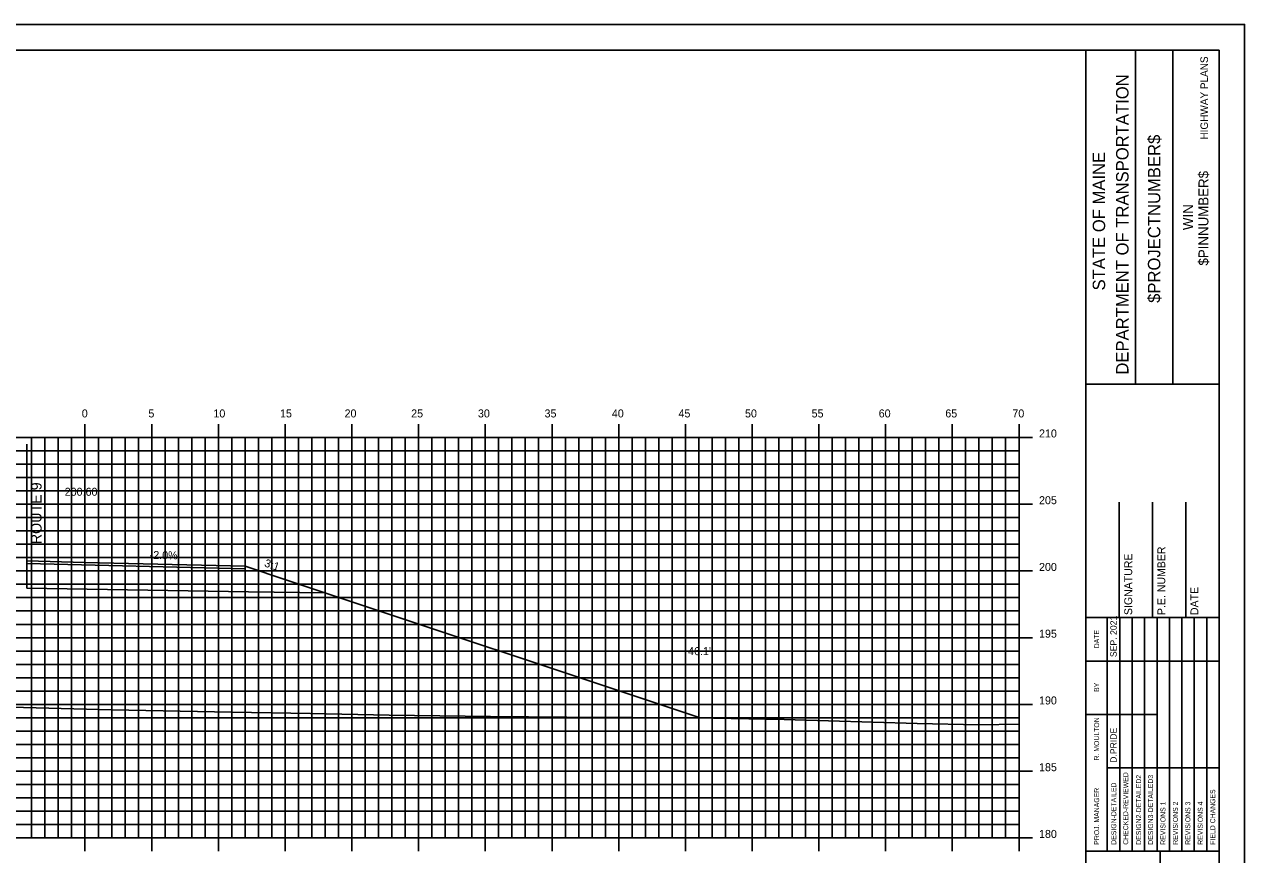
# Model space of a CAD drawing. Extents: x 1723074 to 1723246, y 459560 to 459670.
# Drawn here: x 1723152.9 to 1723244.4, y 459607.4 to 459669.6 of the extents above; entities that cross this region are included whole.
import ezdxf

# ---------------------------------------------------------------- set-up
doc = ezdxf.new("R2010")
doc.units = 0
for name, color, linetype in [('ANNOTATION', 7, 'Continuous'), ('BORDER', 7, 'Continuous'), ('D_Roadway_Centerline_Text', 7, 'Continuous'), ('D_Roadway_Drive_Gravel', 7, 'Continuous'), ('D_Roadway_Edge_Shoulder', 7, 'Continuous'), ('D_Roadway_Edge_TW', 7, 'Continuous'), ('D_Roadway_Pavement', 7, 'Continuous'), ('D_Roadway_SlopeLines', 7, 'Continuous'), ('D_Roadway_SubGrade', 7, 'Continuous'), ('D_Text_Standard', 7, 'Continuous'), ('H_V ANNOTATION', 7, 'Continuous'), ('HIGHWAY_TITLE', 7, 'Continuous'), ('MAJOR', 7, 'Continuous'), ('MINOR', 7, 'Continuous'), ('PLOT BOUNDARY', 7, 'Continuous'), ('S_Roadway_Centerline', 7, 'Continuous')]:
    doc.layers.add(name, color=color, linetype=linetype)

msp = doc.modelspace()

# ---------------------------------------------------------------- linework, layer by layer
at = {"layer": 'BORDER'}
for p, q in [((1723232.447, 459562.613), (1723232.447, 459667.613)), ((1723236.176, 459642.61), (1723236.176, 459667.61)), ((1723238.971, 459642.61), (1723238.971, 459667.61)), ((1723232.448, 459642.607), (1723242.447, 459642.607)), ((1723234.947, 459625.116), (1723234.947, 459633.763)), ((1723237.447, 459625.116), (1723237.447, 459633.763)), ((1723239.947, 459625.116), (1723239.947, 459633.763)), ((1723232.447, 459625.116), (1723242.447, 459625.116)), ((1723232.447, 459607.616), (1723242.447, 459607.616)), ((1723238.038, 459572.616), (1723238.038, 459607.616))]:
    msp.add_line(p, q, dxfattribs=at)
msp.add_lwpolyline([(1723082.447, 459562.613), (1723242.447, 459562.613), (1723242.447, 459667.613), (1723082.447, 459667.613)], close=True, dxfattribs=at)
for points in [[(1723234.062, 459621.866), (1723234.062, 459625.116)], [(1723234.995, 459607.619), (1723234.995, 459625.116)], [(1723235.926, 459625.116), (1723235.926, 459607.619)], [(1723236.858, 459607.619), (1723236.858, 459625.116)], [(1723237.79, 459607.619), (1723237.79, 459625.116)], [(1723238.721, 459607.619), (1723238.721, 459625.116)], [(1723239.653, 459607.619), (1723239.653, 459625.116)], [(1723240.585, 459607.619), (1723240.585, 459625.116)], [(1723241.516, 459607.619), (1723241.516, 459625.116)], [(1723234.063, 459607.619), (1723234.063, 459624.41)], [(1723232.447, 459621.866), (1723242.447, 459621.866)], [(1723232.447, 459617.866), (1723234.063, 459617.866)], [(1723234.062, 459617.866), (1723237.789, 459617.866)], [(1723234.062, 459613.866), (1723242.447, 459613.866)]]:
    msp.add_lwpolyline(points, dxfattribs=at)
at = {"layer": 'D_Roadway_Drive_Gravel'}
msp.add_line((1723169.447, 459628.973), (1723172.638, 459627.909), dxfattribs=at)
at = {"layer": 'D_Roadway_Edge_Shoulder'}
msp.add_line((1723157.447, 459629.258), (1723153.095, 459629.361), dxfattribs=at)
msp.add_lwpolyline([(1723153.095, 459629.165), (1723169.447, 459628.777), (1723169.447, 459628.973)], dxfattribs=at)
at = {"layer": 'D_Roadway_Edge_TW'}
msp.add_line((1723153.095, 459629.415), (1723153.095, 459629.165), dxfattribs=at)
msp.add_line((1723153.095, 459629.415), (1723153.095, 459629.165), dxfattribs=at)
msp.add_line((1723153.095, 459629.415), (1723153.095, 459629.165), dxfattribs=at)
at = {"layer": 'D_Roadway_Pavement'}
msp.add_line((1723153.095, 459629.165), (1723153.095, 459628.748), dxfattribs=at)
msp.add_line((1723153.095, 459629.165), (1723153.095, 459628.748), dxfattribs=at)
msp.add_lwpolyline([(1723153.095, 459629.165), (1723153.095, 459628.748)], dxfattribs=at)
at = {"layer": 'D_Roadway_SlopeLines'}
msp.add_lwpolyline([(1723169.447, 459628.973), (1723172.638, 459627.909), (1723203.544, 459617.607)], dxfattribs=at)
at = {"layer": 'D_Roadway_SubGrade'}
for p, q in [((1723153.095, 459638.114), (1723153.095, 459627.332)), ((1723153.095, 459629.165), (1723153.095, 459627.332)), ((1723157.447, 459629.258), (1723169.447, 459628.973)), ((1723153.095, 459627.332), (1723169.703, 459627.059)), ((1723169.703, 459627.059), (1723175.474, 459626.964))]:
    msp.add_line(p, q, dxfattribs=at)
msp.add_lwpolyline([(1723153.095, 459628.748), (1723153.095, 459629.165), (1723153.095, 459627.332)], dxfattribs=at)
at = {"layer": 'MAJOR'}
for p, q in [((1723157.447, 459639.615), (1723157.447, 459638.613)), ((1723162.447, 459639.615), (1723162.447, 459638.613)), ((1723167.447, 459639.615), (1723167.447, 459638.613)), ((1723172.447, 459639.615), (1723172.447, 459638.613)), ((1723177.447, 459639.615), (1723177.447, 459638.613)), ((1723182.447, 459639.615), (1723182.447, 459638.613)), ((1723187.447, 459639.615), (1723187.447, 459638.613)), ((1723192.447, 459639.615), (1723192.447, 459638.613)), ((1723197.447, 459639.615), (1723197.447, 459638.613)), ((1723202.447, 459639.615), (1723202.447, 459638.613)), ((1723207.447, 459639.615), (1723207.447, 459638.613)), ((1723212.447, 459639.615), (1723212.447, 459638.613)), ((1723217.447, 459639.615), (1723217.447, 459638.613)), ((1723222.447, 459639.615), (1723222.447, 459638.613)), ((1723227.447, 459639.615), (1723227.447, 459638.613)), ((1723087.447, 459638.613), (1723227.447, 459638.613)), ((1723087.447, 459638.613), (1723227.447, 459638.613)), ((1723157.447, 459608.613), (1723157.447, 459638.613)), ((1723162.447, 459608.613), (1723162.447, 459638.613)), ((1723167.447, 459608.613), (1723167.447, 459638.613)), ((1723172.447, 459608.613), (1723172.447, 459638.613)), ((1723177.447, 459608.613), (1723177.447, 459638.613)), ((1723182.447, 459608.613), (1723182.447, 459638.613)), ((1723187.447, 459608.613), (1723187.447, 459638.613)), ((1723192.447, 459608.613), (1723192.447, 459638.613)), ((1723197.447, 459608.613), (1723197.447, 459638.613)), ((1723202.447, 459608.613), (1723202.447, 459638.613)), ((1723207.447, 459608.613), (1723207.447, 459638.613)), ((1723212.447, 459608.613), (1723212.447, 459638.613)), ((1723217.447, 459608.613), (1723217.447, 459638.613)), ((1723222.447, 459608.613), (1723222.447, 459638.613)), ((1723228.449, 459638.613), (1723226.445, 459638.613)), ((1723227.447, 459608.613), (1723227.447, 459638.613)), ((1723227.447, 459608.613), (1723227.447, 459638.613)), ((1723087.447, 459633.613), (1723227.447, 459633.613)), ((1723228.449, 459633.613), (1723226.445, 459633.613)), ((1723087.447, 459628.613), (1723227.447, 459628.613)), ((1723228.449, 459628.613), (1723226.445, 459628.613)), ((1723087.447, 459623.613), (1723227.447, 459623.613)), ((1723228.449, 459623.613), (1723226.445, 459623.613)), ((1723087.447, 459618.613), (1723227.447, 459618.613)), ((1723228.449, 459618.613), (1723226.445, 459618.613)), ((1723087.447, 459613.613), (1723227.447, 459613.613)), ((1723228.449, 459613.613), (1723226.445, 459613.613)), ((1723087.447, 459608.613), (1723227.447, 459608.613)), ((1723087.447, 459608.613), (1723227.447, 459608.613)), ((1723157.447, 459607.611), (1723157.447, 459608.613)), ((1723162.447, 459607.611), (1723162.447, 459608.613)), ((1723167.447, 459607.611), (1723167.447, 459608.613)), ((1723172.447, 459607.611), (1723172.447, 459608.613)), ((1723177.447, 459607.611), (1723177.447, 459608.613)), ((1723182.447, 459607.611), (1723182.447, 459608.613)), ((1723187.447, 459607.611), (1723187.447, 459608.613)), ((1723192.447, 459607.611), (1723192.447, 459608.613)), ((1723197.447, 459607.611), (1723197.447, 459608.613)), ((1723202.447, 459607.611), (1723202.447, 459608.613)), ((1723207.447, 459607.611), (1723207.447, 459608.613)), ((1723212.447, 459607.611), (1723212.447, 459608.613)), ((1723217.447, 459607.611), (1723217.447, 459608.613)), ((1723222.447, 459607.611), (1723222.447, 459608.613)), ((1723228.449, 459608.613), (1723226.445, 459608.613)), ((1723227.447, 459607.611), (1723227.447, 459608.613))]:
    msp.add_line(p, q, dxfattribs=at)
at = {"layer": 'MINOR'}
for p, q in [((1723153.447, 459608.613), (1723153.447, 459638.613)), ((1723154.447, 459608.613), (1723154.447, 459638.613)), ((1723155.447, 459608.613), (1723155.447, 459638.613)), ((1723156.447, 459608.613), (1723156.447, 459638.613)), ((1723158.447, 459608.613), (1723158.447, 459638.613)), ((1723159.447, 459608.613), (1723159.447, 459638.613)), ((1723160.447, 459608.613), (1723160.447, 459638.613)), ((1723161.447, 459608.613), (1723161.447, 459638.613)), ((1723163.447, 459608.613), (1723163.447, 459638.613)), ((1723164.447, 459608.613), (1723164.447, 459638.613)), ((1723165.447, 459608.613), (1723165.447, 459638.613)), ((1723166.447, 459608.613), (1723166.447, 459638.613)), ((1723168.447, 459608.613), (1723168.447, 459638.613)), ((1723169.447, 459608.613), (1723169.447, 459638.613)), ((1723170.447, 459608.613), (1723170.447, 459638.613)), ((1723171.447, 459608.613), (1723171.447, 459638.613)), ((1723173.447, 459608.613), (1723173.447, 459638.613)), ((1723174.447, 459608.613), (1723174.447, 459638.613)), ((1723175.447, 459608.613), (1723175.447, 459638.613)), ((1723176.447, 459608.613), (1723176.447, 459638.613)), ((1723178.447, 459608.613), (1723178.447, 459638.613)), ((1723179.447, 459608.613), (1723179.447, 459638.613)), ((1723180.447, 459608.613), (1723180.447, 459638.613)), ((1723181.447, 459608.613), (1723181.447, 459638.613)), ((1723183.447, 459608.613), (1723183.447, 459638.613)), ((1723184.447, 459608.613), (1723184.447, 459638.613)), ((1723185.447, 459608.613), (1723185.447, 459638.613)), ((1723186.447, 459608.613), (1723186.447, 459638.613)), ((1723188.447, 459608.613), (1723188.447, 459638.613)), ((1723189.447, 459608.613), (1723189.447, 459638.613)), ((1723190.447, 459608.613), (1723190.447, 459638.613)), ((1723191.447, 459608.613), (1723191.447, 459638.613)), ((1723193.447, 459608.613), (1723193.447, 459638.613)), ((1723194.447, 459608.613), (1723194.447, 459638.613)), ((1723195.447, 459608.613), (1723195.447, 459638.613)), ((1723196.447, 459608.613), (1723196.447, 459638.613)), ((1723198.447, 459608.613), (1723198.447, 459638.613)), ((1723199.447, 459608.613), (1723199.447, 459638.613)), ((1723200.447, 459608.613), (1723200.447, 459638.613)), ((1723201.447, 459608.613), (1723201.447, 459638.613)), ((1723203.447, 459608.613), (1723203.447, 459638.613)), ((1723204.447, 459608.613), (1723204.447, 459638.613)), ((1723205.447, 459608.613), (1723205.447, 459638.613)), ((1723206.447, 459608.613), (1723206.447, 459638.613)), ((1723208.447, 459608.613), (1723208.447, 459638.613)), ((1723209.447, 459608.613), (1723209.447, 459638.613)), ((1723210.447, 459608.613), (1723210.447, 459638.613)), ((1723211.447, 459608.613), (1723211.447, 459638.613)), ((1723213.447, 459608.613), (1723213.447, 459638.613)), ((1723214.447, 459608.613), (1723214.447, 459638.613)), ((1723215.447, 459608.613), (1723215.447, 459638.613)), ((1723216.447, 459608.613), (1723216.447, 459638.613)), ((1723218.447, 459608.613), (1723218.447, 459638.613)), ((1723219.447, 459608.613), (1723219.447, 459638.613)), ((1723220.447, 459608.613), (1723220.447, 459638.613)), ((1723221.447, 459608.613), (1723221.447, 459638.613)), ((1723223.447, 459608.613), (1723223.447, 459638.613)), ((1723224.447, 459608.613), (1723224.447, 459638.613)), ((1723225.447, 459608.613), (1723225.447, 459638.613)), ((1723226.447, 459608.613), (1723226.447, 459638.613)), ((1723087.447, 459637.613), (1723227.447, 459637.613)), ((1723227.447, 459637.613), (1723226.445, 459637.613)), ((1723087.447, 459636.613), (1723227.447, 459636.613)), ((1723227.447, 459636.613), (1723226.445, 459636.613)), ((1723087.447, 459635.613), (1723227.447, 459635.613)), ((1723227.447, 459635.613), (1723226.445, 459635.613)), ((1723087.447, 459634.613), (1723227.447, 459634.613)), ((1723227.447, 459634.613), (1723226.445, 459634.613)), ((1723087.447, 459632.613), (1723227.447, 459632.613)), ((1723227.447, 459632.613), (1723226.445, 459632.613)), ((1723087.447, 459631.613), (1723227.447, 459631.613)), ((1723227.447, 459631.613), (1723226.445, 459631.613)), ((1723087.447, 459630.613), (1723227.447, 459630.613)), ((1723227.447, 459630.613), (1723226.445, 459630.613)), ((1723087.447, 459629.613), (1723227.447, 459629.613)), ((1723227.447, 459629.613), (1723226.445, 459629.613)), ((1723087.447, 459627.613), (1723227.447, 459627.613)), ((1723227.447, 459627.613), (1723226.445, 459627.613)), ((1723087.447, 459626.613), (1723227.447, 459626.613)), ((1723227.447, 459626.613), (1723226.445, 459626.613)), ((1723087.447, 459625.613), (1723227.447, 459625.613)), ((1723227.447, 459625.613), (1723226.445, 459625.613)), ((1723087.447, 459624.613), (1723227.447, 459624.613)), ((1723227.447, 459624.613), (1723226.445, 459624.613)), ((1723087.447, 459622.613), (1723227.447, 459622.613)), ((1723227.447, 459622.613), (1723226.445, 459622.613)), ((1723087.447, 459621.613), (1723227.447, 459621.613)), ((1723227.447, 459621.613), (1723226.445, 459621.613)), ((1723087.447, 459620.613), (1723227.447, 459620.613)), ((1723227.447, 459620.613), (1723226.445, 459620.613)), ((1723087.447, 459619.613), (1723227.447, 459619.613)), ((1723227.447, 459619.613), (1723226.445, 459619.613)), ((1723087.447, 459617.613), (1723227.447, 459617.613)), ((1723227.447, 459617.613), (1723226.445, 459617.613)), ((1723087.447, 459616.613), (1723227.447, 459616.613)), ((1723227.447, 459616.613), (1723226.445, 459616.613)), ((1723087.447, 459615.613), (1723227.447, 459615.613)), ((1723227.447, 459615.613), (1723226.445, 459615.613)), ((1723087.447, 459614.613), (1723227.447, 459614.613)), ((1723227.447, 459614.613), (1723226.445, 459614.613)), ((1723087.447, 459612.613), (1723227.447, 459612.613)), ((1723227.447, 459612.613), (1723226.445, 459612.613)), ((1723087.447, 459611.613), (1723227.447, 459611.613)), ((1723227.447, 459611.613), (1723226.445, 459611.613)), ((1723087.447, 459610.613), (1723227.447, 459610.613)), ((1723227.447, 459610.613), (1723226.445, 459610.613)), ((1723087.447, 459609.613), (1723227.447, 459609.613)), ((1723227.447, 459609.613), (1723226.445, 459609.613))]:
    msp.add_line(p, q, dxfattribs=at)
at = {"layer": 'PLOT BOUNDARY'}
msp.add_lwpolyline([(1723074.354, 459559.554), (1723244.354, 459559.554), (1723244.354, 459669.554), (1723074.354, 459669.554)], close=True, dxfattribs=at)
at = {"layer": 'S_Roadway_Centerline'}
msp.add_lwpolyline([(1723087.447, 459619.698), (1723092.56, 459619.553), (1723093.807, 459619.518), (1723094.981, 459619.479), (1723105.508, 459619.487), (1723116.371, 459619.255), (1723116.981, 459619.238), (1723117.588, 459619.206), (1723137.522, 459618.752), (1723140.372, 459618.688), (1723143.416, 459618.636), (1723159.426, 459618.214), (1723168.45, 459618.026), (1723174.35, 459617.946), (1723180.246, 459617.813), (1723187.846, 459617.713), (1723193.553, 459617.67), (1723203.226, 459617.613), (1723209.857, 459617.477), (1723219.824, 459617.188), (1723224.448, 459617.09), (1723227.447, 459617.142)], dxfattribs=at)

# ---------------------------------------------------------------- texts
at = {"layer": 'ANNOTATION'}
for s, height, rotation, p in [('ROUTE 9', 0.8, 90, (1723154.193, 459630.613)), ('-2.0%', 0.6, 358.85424, (1723162.29, 459629.516)), ('3:1', 0.6, 341.56505, (1723170.845, 459628.961))]:
    msp.add_text(s, height=height, rotation=rotation, dxfattribs=at).set_placement(p)
at = {"layer": 'BORDER'}
for s, height, p in [('DEPARTMENT OF TRANSPORTATION', 0.93176, (1723235.654, 459643.319)), ('$PROJECTNUMBER$', 0.93176, (1723238.039, 459648.692)), ('STATE OF MAINE', 0.93176, (1723233.902, 459649.625)), ('$PINNUMBER$', 0.74527, (1723241.643, 459651.488)), ('WIN', 0.7453, (1723240.484, 459654.143)), ('SIGNATURE', 0.5906, (1723235.928, 459625.308)), ('P.E. NUMBER', 0.59055, (1723238.408, 459625.308)), ('DATE', 0.5906, (1723240.888, 459625.308)), ('SEP. 2021', 0.4845, (1723234.77, 459622.161)), ('DATE', 0.3714, (1723233.451, 459622.821)), ('BY', 0.3714, (1723233.451, 459619.551)), ('R. MOULTON', 0.3727, (1723233.451, 459614.418)), ('D.PRIDE', 0.4845, (1723234.77, 459614.239)), ('CHECKED-REVIEWED', 0.37275, (1723235.628, 459608.104)), ('DESIGN-DETAILED', 0.37275, (1723234.734, 459608.104)), ('DESIGN2-DETAILED2', 0.37275, (1723236.597, 459608.104)), ('DESIGN3-DETAILED3', 0.37275, (1723237.492, 459608.104)), ('PROJ. MANAGER', 0.37275, (1723233.451, 459608.104)), ('FIELD CHANGES', 0.37275, (1723242.15, 459608.104)), ('REVISIONS 1', 0.37275, (1723238.423, 459608.104)), ('REVISIONS 2', 0.37275, (1723239.355, 459608.104)), ('REVISIONS 3', 0.37275, (1723240.287, 459608.104)), ('REVISIONS 4', 0.37275, (1723241.218, 459608.104))]:
    msp.add_text(s, height=height, rotation=90, dxfattribs=at).set_placement(p)
at = {"layer": 'D_Roadway_Centerline_Text'}
msp.add_text('200.60', height=0.6, dxfattribs=at).set_placement((1723155.927, 459634.245))
at = {"layer": 'D_Text_Standard'}
msp.add_text("46.1'", height=0.6, dxfattribs=at).set_placement((1723202.648, 459622.307))
at = {"layer": 'H_V ANNOTATION'}
for s, p in [('0', (1723157.206, 459640.113)), ('5', (1723162.198, 459640.113)), ('10', (1723167.072, 459640.113)), ('15', (1723172.064, 459640.113)), ('20', (1723176.901, 459640.113)), ('25', (1723181.893, 459640.113)), ('30', (1723186.896, 459640.113)), ('35', (1723191.888, 459640.113)), ('40', (1723196.933, 459640.113)), ('45', (1723201.925, 459640.113)), ('50', (1723206.912, 459640.113)), ('55', (1723211.904, 459640.113)), ('60', (1723216.933, 459640.113)), ('65', (1723221.925, 459640.113)), ('70', (1723226.949, 459640.113)), ('210', (1723228.947, 459638.613)), ('205', (1723228.947, 459633.613)), ('200', (1723228.947, 459628.613)), ('195', (1723228.947, 459623.613)), ('190', (1723228.947, 459618.613)), ('185', (1723228.947, 459613.613)), ('180', (1723228.947, 459608.613))]:
    msp.add_text(s, height=0.6, dxfattribs=at).set_placement(p)
at = {"layer": 'HIGHWAY_TITLE'}
msp.add_text('HIGHWAY PLANS', height=0.55901, rotation=90, dxfattribs=at).set_placement((1723241.605, 459660.928))

doc.saveas('drawing.dxf')
